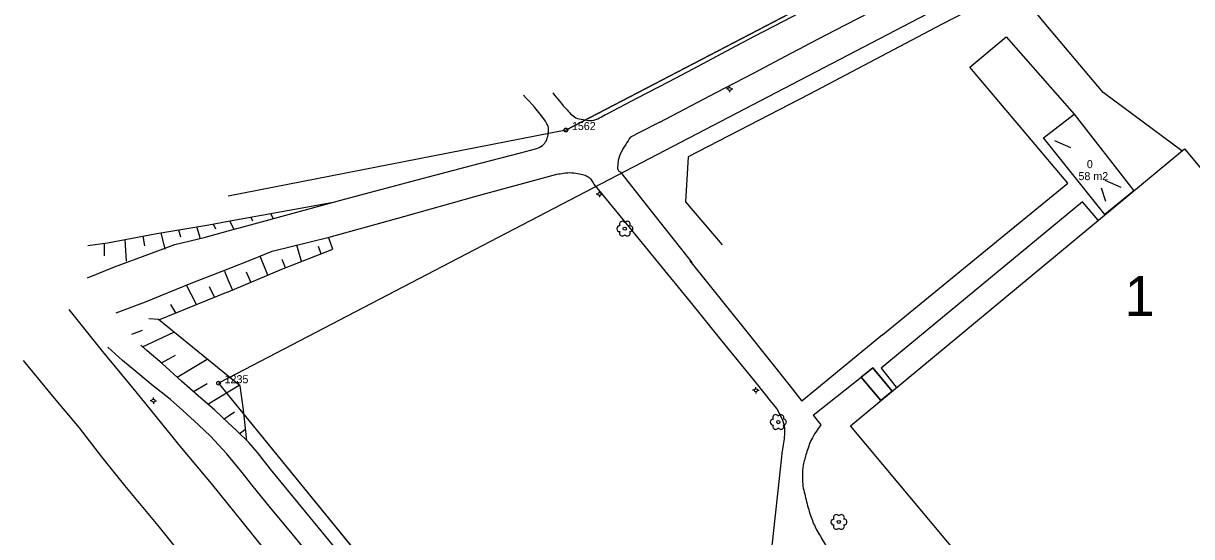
# Model space of a CAD drawing. Extents: x 1517693 to 1518189, y 6494860 to 6495280.
# Drawn here: x 1517692.6 to 1517838.6, y 6495038.2 to 6495102.4 of the extents above; entities that cross this region are included whole.
import ezdxf

# ---------------------------------------------------------------- set-up
doc = ezdxf.new("R2010")
doc.units = 0
for name, color, linetype in [('allmanbygg_symbollinje', 7, 'Continuous'), ('allmanbyggnad', 7, 'Continuous'), ('allmanbyggnad_nummer', 7, 'Continuous'), ('byggnad_areatext', 7, 'Continuous'), ('fastighetsbeteckning', 7, 'Continuous'), ('gc_vag', 7, 'Continuous'), ('grans', 7, 'Continuous'), ('granspunkt', 7, 'Continuous'), ('granspunkt_text', 7, 'Continuous'), ('kvartersgrans', 7, 'Continuous'), ('lovtrad', 7, 'Continuous'), ('slant_skraffering', 7, 'Continuous'), ('slantfot', 7, 'Continuous'), ('slantkron', 7, 'Continuous'), ('staket', 7, 'Continuous'), ('stolpe_belysning', 7, 'Continuous'), ('uthus', 7, 'Continuous'), ('uthus_yta', 7, 'Continuous'), ('vagkant', 7, 'Continuous')]:
    doc.layers.add(name, color=color, linetype=linetype)

msp = doc.modelspace()

# ---------------------------------------------------------------- linework, layer by layer
at = {"layer": 'allmanbygg_symbollinje'}
for p, q in [((1517821.5, 6495087.7), (1517823.5, 6495086.83)), ((1517827.33, 6495081.78), (1517827.85, 6495080.13)), ((1517827.76, 6495082.74), (1517829.76, 6495081.87))]:
    msp.add_line(p, q, dxfattribs=at)
at = {"layer": 'allmanbyggnad'}
for points in [[(1517827.79, 6495078.45), (1517820.11, 6495088.05), (1517823.93, 6495091), (1517831.39, 6495081.44), (1517827.79, 6495078.45)], [(1517795.98, 6495052.03), (1517837.72, 6495086.69), (1517844.24, 6495078.9), (1517844.89, 6495079.4), (1517856.96, 6495064.93), (1517856.28, 6495064.33), (1517862.19, 6495057.11), (1517842.98, 6495041.23), (1517844.57, 6495039.29), (1517839.38, 6495035.07), (1517847.33, 6495025.71), (1517853.22, 6495030.6), (1517862.35, 6495019.75), (1517850.98, 6495010.13), (1517853.38, 6495007.24), (1517840.06, 6494996.19), (1517822.37, 6495017.44), (1517823.84, 6495018.69), (1517795.97, 6495052.03)]]:
    msp.add_lwpolyline(points, dxfattribs=at)
at = {"layer": 'gc_vag'}
for p, q in [((1517799.97, 6495063.4), (1517789.92, 6495055.14)), ((1517791.3, 6495053.39), (1517797.31, 6495058.14))]:
    msp.add_line(p, q, dxfattribs=at)
for points in [[(1517789.99, 6495099.37), (1517794, 6495101.48), (1517798.46, 6495103.77), (1517802.62, 6495105.94), (1517809.04, 6495109.25), (1517812.59, 6495111.02), (1517815.82, 6495112.87)], [(1517764.88, 6495090.69), (1517769.35, 6495093.03), (1517773.3, 6495095.1), (1517776.31, 6495096.66), (1517781.06, 6495099.2), (1517783.99, 6495100.76), (1517787.62, 6495102.64), (1517790.66, 6495104.2)], [(1517799.97, 6495063.4), (1517812.39, 6495073.6), (1517823.16, 6495082.38), (1517810.9, 6495096.88), (1517815.46, 6495100.69), (1517823.93, 6495091)], [(1517772.17, 6495090.02), (1517779.21, 6495093.72), (1517783.85, 6495096.12), (1517788.59, 6495098.62), (1517790.41, 6495099.6)], [(1517772.17, 6495090.02), (1517769.71, 6495088.75), (1517768.49, 6495088.13)], [(1517741.82, 6495082.79), (1517748.6, 6495084.6), (1517754.72, 6495086.16), (1517756.63, 6495086.67)], [(1517740.16, 6495078.22), (1517749.02, 6495080.71), (1517759.28, 6495083.51)], [(1517767.22, 6495083.77), (1517770.63, 6495079.47), (1517776.14, 6495072.45)], [(1517718.21, 6495076.42), (1517720.99, 6495077.19), (1517726.79, 6495078.74), (1517732.75, 6495080.4), (1517741.82, 6495082.79)], [(1517763.9, 6495082.25), (1517767.15, 6495078.3), (1517772, 6495072.37)], [(1517826.96, 6495077.76), (1517824.98, 6495080.06), (1517799.8, 6495059.26), (1517801.71, 6495056.86), (1517801.74, 6495056.82)], [(1517718.21, 6495071.68), (1517721.14, 6495072.83), (1517723.68, 6495073.87), (1517730.83, 6495075.63), (1517740.16, 6495078.22)], [(1517700.61, 6495070.56), (1517703.99, 6495071.93), (1517708.29, 6495073.5), (1517711.55, 6495074.7), (1517715.18, 6495075.58), (1517718.21, 6495076.42)], [(1517775.91, 6495072.65), (1517782.88, 6495064.02), (1517788.43, 6495057)], [(1517704.19, 6495066.15), (1517707.86, 6495067.56), (1517713.58, 6495069.88), (1517718.21, 6495071.68)], [(1517772, 6495072.37), (1517775.96, 6495067.55), (1517779.9, 6495062.62), (1517784.2, 6495057.38)], [(1517718.21, 6495048.34), (1517718.04, 6495048.55), (1517715.97, 6495050.73), (1517714.5, 6495052.16), (1517712.54, 6495053.95), (1517710.97, 6495055.35), (1517708.65, 6495057.17), (1517706.66, 6495058.85), (1517705.01, 6495060.19), (1517703.14, 6495061.88)], [(1517718.21, 6495052.42), (1517716.53, 6495053.98), (1517714.43, 6495055.8), (1517712.37, 6495057.63), (1517709.95, 6495059.83), (1517708.09, 6495061.41), (1517707.3, 6495062.11)], [(1517784.2, 6495057.38), (1517786.12, 6495054.97), (1517786.77, 6495054.17)], [(1517788.43, 6495057), (1517789.92, 6495055.14)], [(1517720.91, 6495049.85), (1517719.2, 6495051.5), (1517718.21, 6495052.42)], [(1517791.3, 6495053.39), (1517792.29, 6495052.15)], [(1517724.81, 6495044.99), (1517723.5, 6495046.63), (1517721.86, 6495048.69), (1517720.78, 6495049.96)], [(1517721.14, 6495044.68), (1517719.93, 6495046.21), (1517718.21, 6495048.34)], [(1517787.46, 6495048.97), (1517787.21, 6495046.63), (1517786.9, 6495043.91)], [(1517740.66, 6495025.65), (1517736.52, 6495030.84), (1517732.32, 6495035.85), (1517728.5, 6495040.55), (1517724.81, 6495044.99)], [(1517737.05, 6495025.22), (1517731.83, 6495031.58), (1517728.92, 6495035.22), (1517726.43, 6495038.23), (1517723.49, 6495041.77), (1517721.14, 6495044.68)], [(1517786.9, 6495043.91), (1517786.54, 6495040.51), (1517786.18, 6495037.43), (1517785.79, 6495034.34), (1517785.53, 6495031.93)]]:
    msp.add_lwpolyline(points, dxfattribs=at)
for points in [[(1517756.63, 6495086.67), (1517757.47, 6495087.09), (1517757.93, 6495087.65), (1517758.19, 6495088.44), (1517758.19, 6495089.49), (1517757.85, 6495090.13), (1517755.1, 6495093.4)], [(1517758.77, 6495093.66), (1517760.56, 6495091.53), (1517761.86, 6495090.48), (1517762.8, 6495090.3), (1517763.67, 6495090.22), (1517764.62, 6495090.55), (1517765.34, 6495090.95)], [(1517768.49, 6495088.13), (1517767.89, 6495087.22), (1517767.24, 6495086.08), (1517766.96, 6495085.25), (1517766.88, 6495084.42), (1517766.93, 6495084), (1517767.22, 6495083.77)], [(1517759.28, 6495083.51), (1517760.12, 6495083.62), (1517761.16, 6495083.69), (1517762.11, 6495083.54), (1517762.84, 6495083.36), (1517763.31, 6495083.1), (1517763.95, 6495082.16)], [(1517786.77, 6495054.17), (1517787.37, 6495053), (1517787.7, 6495051.97), (1517787.73, 6495050.93), (1517787.44, 6495048.88)], [(1517792.29, 6495052.15), (1517791.1, 6495050.31), (1517790.48, 6495048.62), (1517790.09, 6495047.12), (1517789.98, 6495045.77), (1517790.03, 6495044.42)], [(1517790.03, 6495044.5), (1517790.5, 6495042.53), (1517791.07, 6495040.61), (1517791.75, 6495039.03), (1517792.7, 6495037.43), (1517792.99, 6495036.91)]]:
    msp.add_spline(points, degree=3, dxfattribs=at)
at = {"layer": 'grans'}
for p, q in [((1517760.41, 6495089.02), (1517815.51, 6495117.75)), ((1517819.97, 6495111.05), (1517718.21, 6495058)), ((1517760.41, 6495089.02), (1517718.21, 6495080.76)), ((1517718.21, 6495058), (1517717, 6495057.37)), ((1517717, 6495057.37), (1517718.21, 6495055.89)), ((1517718.21, 6495055.89), (1517772.4, 6494989.39))]:
    msp.add_line(p, q, dxfattribs=at)
at = {"layer": 'granspunkt'}
for centre in [(1517760.41, 6495089.02), (1517717, 6495057.37)]:
    msp.add_circle(centre, 0.237, dxfattribs=at)
at = {"layer": 'kvartersgrans'}
for p, q in [((1517819.97, 6495111.05), (1517718.21, 6495058)), ((1517760.41, 6495089.02), (1517718.21, 6495080.76))]:
    msp.add_line(p, q, dxfattribs=at)
for points in [[(1517915.64, 6495201.43), (1517827.1, 6495127.44), (1517815.51, 6495117.75), (1517760.41, 6495089.02)], [(1517718.21, 6495058), (1517717, 6495057.37), (1517718.21, 6495055.89)], [(1517718.21, 6495055.89), (1517772.4, 6494989.39), (1517780.49, 6494980.71), (1517789.65, 6494973.16), (1517799.72, 6494966.88)]]:
    msp.add_lwpolyline(points, dxfattribs=at)
at = {"layer": 'lovtrad'}
for centre in [(1517767.77, 6495076.69), (1517786.96, 6495052.51), (1517794.53, 6495040.02)]:
    msp.add_circle(centre, 0.2, dxfattribs=at)
for centre, start, end in [((1517767.14, 6495076.69), 89.5389, 268.9887), ((1517767.46, 6495077.25), 29.1347, 212.3057), ((1517768.09, 6495077.25), 329.1331, 150.8613), ((1517768.41, 6495076.69), 269.1508, 90.8733), ((1517767.46, 6495076.14), 150.5831, 330.865), ((1517768.09, 6495076.14), 209.1844, 30.8583), ((1517786.33, 6495052.5), 89.5389, 268.9887), ((1517786.64, 6495053.07), 29.1347, 212.3057), ((1517787.28, 6495053.07), 329.1331, 150.8613), ((1517787.6, 6495052.51), 269.1508, 90.8733), ((1517786.64, 6495051.96), 150.5831, 330.865), ((1517787.28, 6495051.96), 209.1844, 30.8583), ((1517794.21, 6495040.57), 29.1347, 212.3057), ((1517794.85, 6495040.57), 329.1331, 150.8613), ((1517793.9, 6495040.01), 89.5389, 268.9887), ((1517794.21, 6495039.47), 150.5831, 330.865), ((1517794.85, 6495039.47), 209.1844, 30.8583), ((1517795.17, 6495040.02), 269.1508, 90.8733)]:
    msp.add_arc(centre, 0.366, start, end, dxfattribs=at)
at = {"layer": 'slant_skraffering'}
for p, q in [((1517723.51, 6495078.58), (1517723.84, 6495077.95)), ((1517716.34, 6495077.28), (1517716.61, 6495076.65)), ((1517718.38, 6495077.65), (1517718.9, 6495076.61)), ((1517721.04, 6495078.13), (1517721.25, 6495077.67)), ((1517707.55, 6495075.77), (1517707.74, 6495074.53)), ((1517709.78, 6495076.18), (1517710.27, 6495074.12)), ((1517711.98, 6495076.55), (1517712.25, 6495075.69)), ((1517714.29, 6495076.85), (1517714.69, 6495075.46)), ((1517702.69, 6495074.87), (1517702.7, 6495073.3)), ((1517705.28, 6495075.34), (1517705.43, 6495072.62)), ((1517727.36, 6495072.59), (1517726.77, 6495074.63)), ((1517729.82, 6495073.55), (1517729.51, 6495074.46)), ((1517723.14, 6495070.89), (1517722.19, 6495073.26)), ((1517725.37, 6495071.81), (1517724.94, 6495072.82)), ((1517721.02, 6495070), (1517720.5, 6495071.25)), ((1517718.74, 6495069.04), (1517718.21, 6495070.3)), ((1517714.26, 6495067.21), (1517712.99, 6495069.64)), ((1517716.5, 6495068.12), (1517715.86, 6495069.41)), ((1517711.65, 6495066.16), (1517711.02, 6495067.23)), ((1517706.16, 6495063.48), (1517707.47, 6495064.02)), ((1517707.5, 6495061.93), (1517711.42, 6495063.76)), ((1517709.86, 6495059.91), (1517711.63, 6495060.88)), ((1517711.82, 6495058.13), (1517715.59, 6495060.36)), ((1517713.85, 6495056.32), (1517715.59, 6495057.33)), ((1517718.21, 6495056.29), (1517719.58, 6495057.12)), ((1517715.66, 6495054.74), (1517718.21, 6495056.29)), ((1517718.21, 6495053.26), (1517719, 6495053.78)), ((1517717.68, 6495052.91), (1517718.21, 6495053.26)), ((1517719.61, 6495051.1), (1517720.38, 6495051.64))]:
    msp.add_line(p, q, dxfattribs=at)
msp.add_lwpolyline([(1517718.21, 6495070.3), (1517717.77, 6495071.32), (1517717.78, 6495071.25), (1517717.78, 6495071.25)], dxfattribs=at)
at = {"layer": 'slantfot'}
for points in [[(1517718.21, 6495058.24), (1517709.5, 6495065.32), (1517708.29, 6495065.42)], [(1517720.54, 6495050.21), (1517720.11, 6495054.02), (1517719.69, 6495057.03), (1517718.21, 6495058.24)]]:
    msp.add_lwpolyline(points, dxfattribs=at)
at = {"layer": 'slantkron'}
msp.add_line((1517700.64, 6495074.59), (1517703.13, 6495074.93), dxfattribs=at)
for points in [[(1517718.21, 6495077.62), (1517722.38, 6495078.38), (1517729.28, 6495079.62), (1517731.34, 6495080.01)], [(1517703.11, 6495074.93), (1517709.27, 6495076.1), (1517715.8, 6495077.19), (1517718.21, 6495077.62)], [(1517718.21, 6495068.81), (1517724.92, 6495071.64), (1517731.3, 6495074.13), (1517730.74, 6495075.61)], [(1517709.52, 6495065.3), (1517718.03, 6495068.74), (1517718.21, 6495068.81)]]:
    msp.add_lwpolyline(points, dxfattribs=at)
at = {"layer": 'staket'}
msp.add_line((1517837.41, 6495086.43), (1517827.55, 6495093.72), dxfattribs=at)
for points in [[(1517827.55, 6495093.72), (1517820.39, 6495102.2), (1517816.53, 6495106.95), (1517807.35, 6495102.2), (1517790.87, 6495093.51)], [(1517790.87, 6495093.51), (1517775.7, 6495085.69), (1517775.37, 6495080.06), (1517779.93, 6495074.67)]]:
    msp.add_lwpolyline(points, dxfattribs=at)
at = {"layer": 'stolpe_belysning'}
for p, q in [((1517780.87, 6495094.36), (1517780.87, 6495094.56)), ((1517780.67, 6495094.16), (1517780.47, 6495094.16)), ((1517780.87, 6495093.96), (1517780.87, 6495093.76)), ((1517781.07, 6495094.16), (1517781.27, 6495094.16)), ((1517764.61, 6495081.22), (1517764.61, 6495081.42)), ((1517764.41, 6495081.02), (1517764.21, 6495081.02)), ((1517764.61, 6495080.82), (1517764.61, 6495080.62)), ((1517764.81, 6495081.02), (1517765.01, 6495081.02)), ((1517784.15, 6495056.68), (1517784.15, 6495056.88)), ((1517708.65, 6495055.18), (1517708.45, 6495055.18)), ((1517708.85, 6495055.38), (1517708.85, 6495055.58)), ((1517709.05, 6495055.18), (1517709.25, 6495055.18)), ((1517783.95, 6495056.48), (1517783.75, 6495056.48)), ((1517784.15, 6495056.28), (1517784.15, 6495056.08)), ((1517784.35, 6495056.48), (1517784.55, 6495056.48)), ((1517708.85, 6495054.98), (1517708.85, 6495054.78))]:
    msp.add_line(p, q, dxfattribs=at)
for centre in [(1517780.87, 6495094.16), (1517764.61, 6495081.02), (1517784.15, 6495056.48), (1517708.85, 6495055.18)]:
    msp.add_circle(centre, 0.2, dxfattribs=at)
at = {"layer": 'uthus'}
msp.add_lwpolyline([(1517801.21, 6495056.38), (1517798.77, 6495059.31), (1517797.31, 6495058.14), (1517799.79, 6495055.2), (1517801.21, 6495056.38)], dxfattribs=at)
at = {"layer": 'uthus_yta'}
msp.add_lwpolyline([(1517799.79, 6495055.2), (1517797.31, 6495058.14), (1517798.77, 6495059.31), (1517801.21, 6495056.38)], close=True, dxfattribs=at)
at = {"layer": 'vagkant'}
for points in [[(1517712.42, 6495049.25), (1517706.71, 6495056.31), (1517702.33, 6495061.6), (1517698.34, 6495066.58)], [(1517702.42, 6495048.15), (1517699.6, 6495051.79), (1517696.48, 6495055.51), (1517692.6, 6495060.19)], [(1517718.21, 6495042.23), (1517716.12, 6495044.82), (1517712.42, 6495049.25)], [(1517718.21, 6495028.61), (1517716.29, 6495031.02), (1517713.45, 6495034.56), (1517709.43, 6495039.57), (1517705.29, 6495044.58), (1517702.42, 6495048.15)], [(1517728.85, 6495029.05), (1517725.08, 6495033.71), (1517719.93, 6495040.09), (1517718.21, 6495042.23)]]:
    msp.add_lwpolyline(points, dxfattribs=at)

# ---------------------------------------------------------------- texts
at = {"layer": 'allmanbyggnad_nummer'}
msp.add_text('0', height=1, dxfattribs=at).set_placement((1517825.53, 6495084.26))
at = {"layer": 'byggnad_areatext'}
msp.add_text('58 m2', height=1, dxfattribs=at).set_placement((1517824.48, 6495082.76))
at = {"layer": 'fastighetsbeteckning'}
msp.add_text('1', height=5, rotation=0.0021, dxfattribs=at).set_placement((1517830.26, 6495065.76))
at = {"layer": 'granspunkt_text'}
for s, p in [('1562', (1517761.16, 6495089.02)), ('1235', (1517717.75, 6495057.37))]:
    msp.add_text(s, height=1, dxfattribs=at).set_placement(p)

doc.saveas('drawing.dxf')
